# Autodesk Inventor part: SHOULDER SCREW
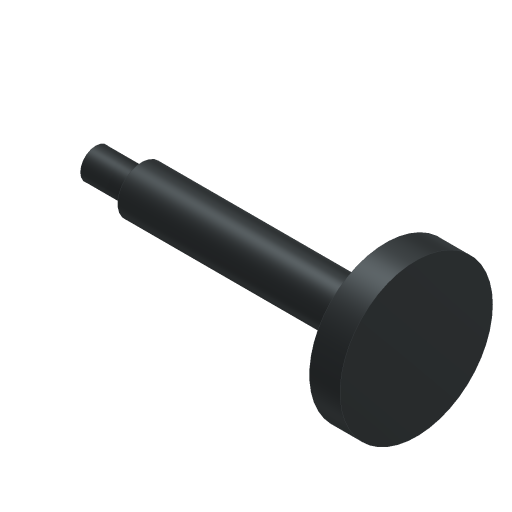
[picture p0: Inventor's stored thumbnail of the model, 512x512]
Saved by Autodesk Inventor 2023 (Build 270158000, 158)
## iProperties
Created: 2016-05
Part Number: SHOULDER SCREW
Material: Iron, Cast
Document SubType Name: Modeling
Designer: CADCIM
Density: 7.15 g/cm^3
Appearance: Iron Gray
Mass: 16.5435 g
Surface Area: 15.8336 cm^2
Volume: 2.31378 cm^3
Author: CADCIM
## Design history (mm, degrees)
sketch "Sketch1"
  geometry: L1 (0, 0)-(0, 2); L2 (0, 2)-(6, 2); L3 (6, 2)-(6, 3.125); L4 (6, 3.125)-(38, 3.125); L5 (38, 3.125)-(38, 10); L6 (38, 10)-(42, 10); L7 (42, 10)-(42, 0); L8 (42, 0)-(0, 0)
  constraints: 16 end point, 7 perpendicular, 1 vertical
  dimensions: "d0" = 4 diameter of L2 L8; "d1" = 6.25 diameter of L4 L8; "d2" = 20 diameter of L6 L8; "d3" = 32 distance between parallel lines of L5 L3; "d4" = 42 distance between parallel lines of L1 L7; "d5" = 4 distance of L5.end L6.end
revolve "Revolution1" sketch "Sketch1" stored, may be unused: angle "d6" = 90 deg
body "Solid1"
